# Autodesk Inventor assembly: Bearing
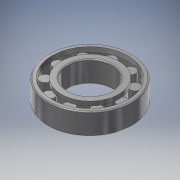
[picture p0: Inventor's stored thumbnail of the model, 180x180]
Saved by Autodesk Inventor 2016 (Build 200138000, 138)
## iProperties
Created: 2015-08
Part Number: Bearing
Document SubType Name: Assembly
Designer: stank
Mass: 72.9462 g
Surface Area: 85.1408 cm^2
Volume: 9.29251 cm^3
Density: 7.85 g/cm^3
ClientObjectVersion: 1
Author: stank
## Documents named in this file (2)
- E:\Turbokompr\Sklop turbokompresora\Design Accelerator\Bearing1.iam
- C:\Users\stank\Documents\Inventor\Content Center Files\R2016\en-US\BS 292 (V)\BS 292_ Part 1 - N 1005 - 25 x 47 x 12.ipt
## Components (1 placed, 1 different names)
1. BS 292: Part 1 (V) (Metric) N 1005 - 25 x 47 x 12:1
